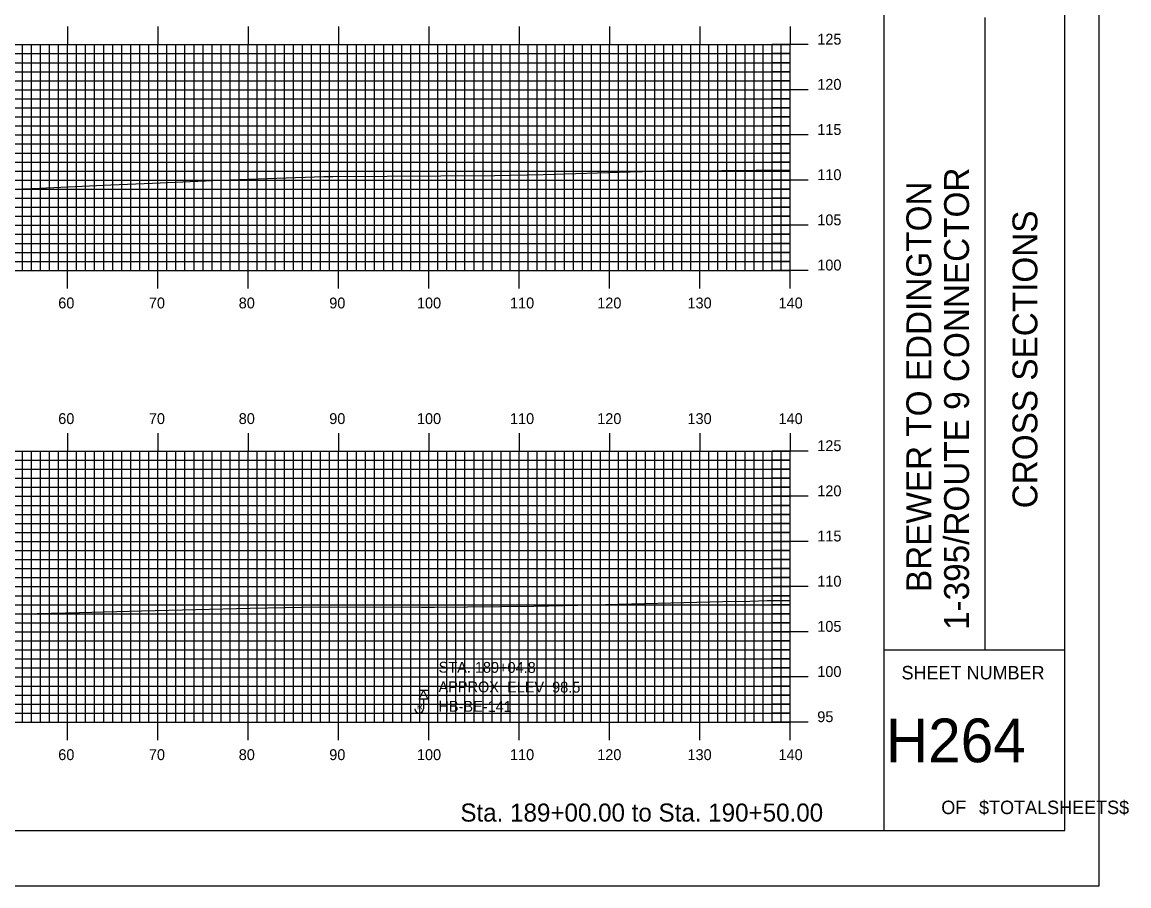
# Model space of a CAD drawing. Extents: x 1788156 to 1788500, y 442591 to 442811.
# Drawn here: x 1788377.1 to 1788499.6, y 442590.5 to 442686.2 of the extents above; entities that cross this region are included whole.
import ezdxf

# ---------------------------------------------------------------- set-up
doc = ezdxf.new("R2010")
doc.units = 0
for name, color, linetype in [('BORDER', 7, 'Continuous'), ('BORING - NO REFUSAL', 7, 'Continuous'), ('BORING - REFUSAL', 7, 'Continuous'), ('H_V ANNOTATION', 7, 'Continuous'), ('MAJOR', 7, 'Continuous'), ('MINOR', 7, 'Continuous'), ('PLOT BOUNDARY', 7, 'Continuous'), ('S_Roadway_Centerline', 7, 'Continuous')]:
    doc.layers.add(name, color=color, linetype=linetype)

msp = doc.modelspace()

# ---------------------------------------------------------------- linework, layer by layer
at = {"layer": 'BORDER'}
for p, q in [((1788472.53, 442596.67), (1788472.53, 442806.67)), ((1788483.71, 442616.67), (1788483.71, 442686.67)), ((1788472.53, 442616.67), (1788492.53, 442616.67))]:
    msp.add_line(p, q, dxfattribs=at)
msp.add_lwpolyline([(1788172.53, 442596.67), (1788492.53, 442596.67), (1788492.53, 442806.67), (1788172.53, 442806.67)], close=True, dxfattribs=at)
at = {"layer": 'BORING - NO REFUSAL'}
for p, q in [((1788422.01, 442612.17), (1788421.05, 442612.17)), ((1788421.53, 442611.21), (1788421.53, 442610.15))]:
    msp.add_line(p, q, dxfattribs=at)
msp.add_lwpolyline([(1788421.53, 442612.17), (1788422.01, 442611.21), (1788421.05, 442611.21)], close=True, dxfattribs=at)
msp.add_arc((1788421.05, 442610.15), 0.485, 180, 0, dxfattribs=at)
at = {"layer": 'MAJOR'}
for p, q in [((1788382.13, 442685.67), (1788382.13, 442683.67)), ((1788392.13, 442685.67), (1788392.13, 442683.67)), ((1788402.13, 442685.67), (1788402.13, 442683.67)), ((1788412.13, 442685.67), (1788412.13, 442683.67)), ((1788422.13, 442685.67), (1788422.13, 442683.67)), ((1788432.13, 442685.67), (1788432.13, 442683.67)), ((1788442.13, 442685.67), (1788442.13, 442683.67)), ((1788452.13, 442685.67), (1788452.13, 442683.67)), ((1788462.13, 442685.67), (1788462.13, 442683.67)), ((1788182.13, 442683.67), (1788462.13, 442683.67)), ((1788182.13, 442683.67), (1788462.13, 442683.67)), ((1788382.13, 442658.67), (1788382.13, 442683.67)), ((1788392.13, 442658.67), (1788392.13, 442683.67)), ((1788402.13, 442658.67), (1788402.13, 442683.67)), ((1788412.13, 442658.67), (1788412.13, 442683.67)), ((1788422.13, 442658.67), (1788422.13, 442683.67)), ((1788432.13, 442658.67), (1788432.13, 442683.67)), ((1788442.13, 442658.67), (1788442.13, 442683.67)), ((1788452.13, 442658.67), (1788452.13, 442683.67)), ((1788464.13, 442683.67), (1788460.13, 442683.67)), ((1788462.13, 442658.67), (1788462.13, 442683.67)), ((1788462.13, 442658.67), (1788462.13, 442683.67)), ((1788182.13, 442678.67), (1788462.13, 442678.67)), ((1788464.13, 442678.67), (1788460.13, 442678.67)), ((1788182.13, 442673.67), (1788462.13, 442673.67)), ((1788464.13, 442673.67), (1788460.13, 442673.67)), ((1788182.13, 442668.67), (1788462.13, 442668.67)), ((1788464.13, 442668.67), (1788460.13, 442668.67)), ((1788182.13, 442663.67), (1788462.13, 442663.67)), ((1788464.13, 442663.67), (1788460.13, 442663.67)), ((1788182.13, 442658.67), (1788462.13, 442658.67)), ((1788182.13, 442658.67), (1788462.13, 442658.67)), ((1788382.13, 442656.66), (1788382.13, 442658.67)), ((1788392.13, 442656.66), (1788392.13, 442658.67)), ((1788402.13, 442656.66), (1788402.13, 442658.67)), ((1788412.13, 442656.66), (1788412.13, 442658.67)), ((1788422.13, 442656.66), (1788422.13, 442658.67)), ((1788432.13, 442656.66), (1788432.13, 442658.67)), ((1788442.13, 442656.66), (1788442.13, 442658.67)), ((1788452.13, 442656.66), (1788452.13, 442658.67)), ((1788464.13, 442658.67), (1788460.13, 442658.67)), ((1788462.13, 442656.66), (1788462.13, 442658.67)), ((1788382.13, 442640.67), (1788382.13, 442638.67)), ((1788392.13, 442640.67), (1788392.13, 442638.67)), ((1788402.13, 442640.67), (1788402.13, 442638.67)), ((1788412.13, 442640.67), (1788412.13, 442638.67)), ((1788422.13, 442640.67), (1788422.13, 442638.67)), ((1788432.13, 442640.67), (1788432.13, 442638.67)), ((1788442.13, 442640.67), (1788442.13, 442638.67)), ((1788452.13, 442640.67), (1788452.13, 442638.67)), ((1788462.13, 442640.67), (1788462.13, 442638.67)), ((1788182.13, 442638.67), (1788462.13, 442638.67)), ((1788182.13, 442638.67), (1788462.13, 442638.67)), ((1788382.13, 442608.67), (1788382.13, 442638.67)), ((1788392.13, 442608.67), (1788392.13, 442638.67)), ((1788402.13, 442608.67), (1788402.13, 442638.67)), ((1788412.13, 442608.67), (1788412.13, 442638.67)), ((1788422.13, 442608.67), (1788422.13, 442638.67)), ((1788432.13, 442608.67), (1788432.13, 442638.67)), ((1788442.13, 442608.67), (1788442.13, 442638.67)), ((1788452.13, 442608.67), (1788452.13, 442638.67)), ((1788464.13, 442638.67), (1788460.13, 442638.67)), ((1788462.13, 442608.67), (1788462.13, 442638.67)), ((1788462.13, 442608.67), (1788462.13, 442638.67)), ((1788182.13, 442633.67), (1788462.13, 442633.67)), ((1788464.13, 442633.67), (1788460.13, 442633.67)), ((1788182.13, 442628.67), (1788462.13, 442628.67)), ((1788464.13, 442628.67), (1788460.13, 442628.67)), ((1788182.13, 442623.67), (1788462.13, 442623.67)), ((1788464.13, 442623.67), (1788460.13, 442623.67)), ((1788182.13, 442618.67), (1788462.13, 442618.67)), ((1788464.13, 442618.67), (1788460.13, 442618.67)), ((1788182.13, 442613.67), (1788462.13, 442613.67)), ((1788464.13, 442613.67), (1788460.13, 442613.67)), ((1788182.13, 442608.67), (1788462.13, 442608.67)), ((1788182.13, 442608.67), (1788462.13, 442608.67)), ((1788382.13, 442606.66), (1788382.13, 442608.67)), ((1788392.13, 442606.66), (1788392.13, 442608.67)), ((1788402.13, 442606.66), (1788402.13, 442608.67)), ((1788412.13, 442606.66), (1788412.13, 442608.67)), ((1788422.13, 442606.66), (1788422.13, 442608.67)), ((1788432.13, 442606.66), (1788432.13, 442608.67)), ((1788442.13, 442606.66), (1788442.13, 442608.67)), ((1788452.13, 442606.66), (1788452.13, 442608.67)), ((1788464.13, 442608.67), (1788460.13, 442608.67)), ((1788462.13, 442606.66), (1788462.13, 442608.67))]:
    msp.add_line(p, q, dxfattribs=at)
at = {"layer": 'MINOR'}
for p, q in [((1788377.13, 442658.67), (1788377.13, 442683.67)), ((1788378.13, 442658.67), (1788378.13, 442683.67)), ((1788379.13, 442658.67), (1788379.13, 442683.67)), ((1788380.13, 442658.67), (1788380.13, 442683.67)), ((1788381.13, 442658.67), (1788381.13, 442683.67)), ((1788383.13, 442658.67), (1788383.13, 442683.67)), ((1788384.13, 442658.67), (1788384.13, 442683.67)), ((1788385.13, 442658.67), (1788385.13, 442683.67)), ((1788386.13, 442658.67), (1788386.13, 442683.67)), ((1788387.13, 442658.67), (1788387.13, 442683.67)), ((1788388.13, 442658.67), (1788388.13, 442683.67)), ((1788389.13, 442658.67), (1788389.13, 442683.67)), ((1788390.13, 442658.67), (1788390.13, 442683.67)), ((1788391.13, 442658.67), (1788391.13, 442683.67)), ((1788393.13, 442658.67), (1788393.13, 442683.67)), ((1788394.13, 442658.67), (1788394.13, 442683.67)), ((1788395.13, 442658.67), (1788395.13, 442683.67)), ((1788396.13, 442658.67), (1788396.13, 442683.67)), ((1788397.13, 442658.67), (1788397.13, 442683.67)), ((1788398.13, 442658.67), (1788398.13, 442683.67)), ((1788399.13, 442658.67), (1788399.13, 442683.67)), ((1788400.13, 442658.67), (1788400.13, 442683.67)), ((1788401.13, 442658.67), (1788401.13, 442683.67)), ((1788403.13, 442658.67), (1788403.13, 442683.67)), ((1788404.13, 442658.67), (1788404.13, 442683.67)), ((1788405.13, 442658.67), (1788405.13, 442683.67)), ((1788406.13, 442658.67), (1788406.13, 442683.67)), ((1788407.13, 442658.67), (1788407.13, 442683.67)), ((1788408.13, 442658.67), (1788408.13, 442683.67)), ((1788409.13, 442658.67), (1788409.13, 442683.67)), ((1788410.13, 442658.67), (1788410.13, 442683.67)), ((1788411.13, 442658.67), (1788411.13, 442683.67)), ((1788413.13, 442658.67), (1788413.13, 442683.67)), ((1788414.13, 442658.67), (1788414.13, 442683.67)), ((1788415.13, 442658.67), (1788415.13, 442683.67)), ((1788416.13, 442658.67), (1788416.13, 442683.67)), ((1788417.13, 442658.67), (1788417.13, 442683.67)), ((1788418.13, 442658.67), (1788418.13, 442683.67)), ((1788419.13, 442658.67), (1788419.13, 442683.67)), ((1788420.13, 442658.67), (1788420.13, 442683.67)), ((1788421.13, 442658.67), (1788421.13, 442683.67)), ((1788423.13, 442658.67), (1788423.13, 442683.67)), ((1788424.13, 442658.67), (1788424.13, 442683.67)), ((1788425.13, 442658.67), (1788425.13, 442683.67)), ((1788426.13, 442658.67), (1788426.13, 442683.67)), ((1788427.13, 442658.67), (1788427.13, 442683.67)), ((1788428.13, 442658.67), (1788428.13, 442683.67)), ((1788429.13, 442658.67), (1788429.13, 442683.67)), ((1788430.13, 442658.67), (1788430.13, 442683.67)), ((1788431.13, 442658.67), (1788431.13, 442683.67)), ((1788433.13, 442658.67), (1788433.13, 442683.67)), ((1788434.13, 442658.67), (1788434.13, 442683.67)), ((1788435.13, 442658.67), (1788435.13, 442683.67)), ((1788436.13, 442658.67), (1788436.13, 442683.67)), ((1788437.13, 442658.67), (1788437.13, 442683.67)), ((1788438.13, 442658.67), (1788438.13, 442683.67)), ((1788439.13, 442658.67), (1788439.13, 442683.67)), ((1788440.13, 442658.67), (1788440.13, 442683.67)), ((1788441.13, 442658.67), (1788441.13, 442683.67)), ((1788443.13, 442658.67), (1788443.13, 442683.67)), ((1788444.13, 442658.67), (1788444.13, 442683.67)), ((1788445.13, 442658.67), (1788445.13, 442683.67)), ((1788446.13, 442658.67), (1788446.13, 442683.67)), ((1788447.13, 442658.67), (1788447.13, 442683.67)), ((1788448.13, 442658.67), (1788448.13, 442683.67)), ((1788449.13, 442658.67), (1788449.13, 442683.67)), ((1788450.13, 442658.67), (1788450.13, 442683.67)), ((1788451.13, 442658.67), (1788451.13, 442683.67)), ((1788453.13, 442658.67), (1788453.13, 442683.67)), ((1788454.13, 442658.67), (1788454.13, 442683.67)), ((1788455.13, 442658.67), (1788455.13, 442683.67)), ((1788456.13, 442658.67), (1788456.13, 442683.67)), ((1788457.13, 442658.67), (1788457.13, 442683.67)), ((1788458.13, 442658.67), (1788458.13, 442683.67)), ((1788459.13, 442658.67), (1788459.13, 442683.67)), ((1788460.13, 442658.67), (1788460.13, 442683.67)), ((1788461.13, 442658.67), (1788461.13, 442683.67)), ((1788182.13, 442682.67), (1788462.13, 442682.67)), ((1788182.13, 442681.67), (1788462.13, 442681.67)), ((1788462.13, 442682.67), (1788460.13, 442682.67)), ((1788462.13, 442681.67), (1788460.13, 442681.67)), ((1788182.13, 442680.67), (1788462.13, 442680.67)), ((1788462.13, 442680.67), (1788460.13, 442680.67)), ((1788182.13, 442679.67), (1788462.13, 442679.67)), ((1788462.13, 442679.67), (1788460.13, 442679.67)), ((1788182.13, 442677.67), (1788462.13, 442677.67)), ((1788462.13, 442677.67), (1788460.13, 442677.67)), ((1788182.13, 442676.67), (1788462.13, 442676.67)), ((1788182.13, 442675.67), (1788462.13, 442675.67)), ((1788462.13, 442676.67), (1788460.13, 442676.67)), ((1788462.13, 442675.67), (1788460.13, 442675.67)), ((1788182.13, 442674.67), (1788462.13, 442674.67)), ((1788462.13, 442674.67), (1788460.13, 442674.67)), ((1788182.13, 442672.67), (1788462.13, 442672.67)), ((1788462.13, 442672.67), (1788460.13, 442672.67)), ((1788182.13, 442671.67), (1788462.13, 442671.67)), ((1788182.13, 442670.67), (1788462.13, 442670.67)), ((1788462.13, 442671.67), (1788460.13, 442671.67)), ((1788462.13, 442670.67), (1788460.13, 442670.67)), ((1788182.13, 442669.67), (1788462.13, 442669.67)), ((1788462.13, 442669.67), (1788460.13, 442669.67)), ((1788182.13, 442667.67), (1788462.13, 442667.67)), ((1788462.13, 442667.67), (1788460.13, 442667.67)), ((1788182.13, 442666.67), (1788462.13, 442666.67)), ((1788462.13, 442666.67), (1788460.13, 442666.67)), ((1788182.13, 442665.67), (1788462.13, 442665.67)), ((1788182.13, 442664.67), (1788462.13, 442664.67)), ((1788462.13, 442665.67), (1788460.13, 442665.67)), ((1788462.13, 442664.67), (1788460.13, 442664.67)), ((1788182.13, 442662.67), (1788462.13, 442662.67)), ((1788462.13, 442662.67), (1788460.13, 442662.67)), ((1788182.13, 442661.67), (1788462.13, 442661.67)), ((1788462.13, 442661.67), (1788460.13, 442661.67)), ((1788182.13, 442660.67), (1788462.13, 442660.67)), ((1788182.13, 442659.67), (1788462.13, 442659.67)), ((1788462.13, 442660.67), (1788460.13, 442660.67)), ((1788462.13, 442659.67), (1788460.13, 442659.67)), ((1788182.13, 442637.67), (1788462.13, 442637.67)), ((1788377.13, 442608.67), (1788377.13, 442638.67)), ((1788378.13, 442608.67), (1788378.13, 442638.67)), ((1788379.13, 442608.67), (1788379.13, 442638.67)), ((1788380.13, 442608.67), (1788380.13, 442638.67)), ((1788381.13, 442608.67), (1788381.13, 442638.67)), ((1788383.13, 442608.67), (1788383.13, 442638.67)), ((1788384.13, 442608.67), (1788384.13, 442638.67)), ((1788385.13, 442608.67), (1788385.13, 442638.67)), ((1788386.13, 442608.67), (1788386.13, 442638.67)), ((1788387.13, 442608.67), (1788387.13, 442638.67)), ((1788388.13, 442608.67), (1788388.13, 442638.67)), ((1788389.13, 442608.67), (1788389.13, 442638.67)), ((1788390.13, 442608.67), (1788390.13, 442638.67)), ((1788391.13, 442608.67), (1788391.13, 442638.67)), ((1788393.13, 442608.67), (1788393.13, 442638.67)), ((1788394.13, 442608.67), (1788394.13, 442638.67)), ((1788395.13, 442608.67), (1788395.13, 442638.67)), ((1788396.13, 442608.67), (1788396.13, 442638.67)), ((1788397.13, 442608.67), (1788397.13, 442638.67)), ((1788398.13, 442608.67), (1788398.13, 442638.67)), ((1788399.13, 442608.67), (1788399.13, 442638.67)), ((1788400.13, 442608.67), (1788400.13, 442638.67)), ((1788401.13, 442608.67), (1788401.13, 442638.67)), ((1788403.13, 442608.67), (1788403.13, 442638.67)), ((1788404.13, 442608.67), (1788404.13, 442638.67)), ((1788405.13, 442608.67), (1788405.13, 442638.67)), ((1788406.13, 442608.67), (1788406.13, 442638.67)), ((1788407.13, 442608.67), (1788407.13, 442638.67)), ((1788408.13, 442608.67), (1788408.13, 442638.67)), ((1788409.13, 442608.67), (1788409.13, 442638.67)), ((1788410.13, 442608.67), (1788410.13, 442638.67)), ((1788411.13, 442608.67), (1788411.13, 442638.67)), ((1788413.13, 442608.67), (1788413.13, 442638.67)), ((1788414.13, 442608.67), (1788414.13, 442638.67)), ((1788415.13, 442608.67), (1788415.13, 442638.67)), ((1788416.13, 442608.67), (1788416.13, 442638.67)), ((1788417.13, 442608.67), (1788417.13, 442638.67)), ((1788418.13, 442608.67), (1788418.13, 442638.67)), ((1788419.13, 442608.67), (1788419.13, 442638.67)), ((1788420.13, 442608.67), (1788420.13, 442638.67)), ((1788421.13, 442608.67), (1788421.13, 442638.67)), ((1788423.13, 442608.67), (1788423.13, 442638.67)), ((1788424.13, 442608.67), (1788424.13, 442638.67)), ((1788425.13, 442608.67), (1788425.13, 442638.67)), ((1788426.13, 442608.67), (1788426.13, 442638.67)), ((1788427.13, 442608.67), (1788427.13, 442638.67)), ((1788428.13, 442608.67), (1788428.13, 442638.67)), ((1788429.13, 442608.67), (1788429.13, 442638.67)), ((1788430.13, 442608.67), (1788430.13, 442638.67)), ((1788431.13, 442608.67), (1788431.13, 442638.67)), ((1788433.13, 442608.67), (1788433.13, 442638.67)), ((1788434.13, 442608.67), (1788434.13, 442638.67)), ((1788435.13, 442608.67), (1788435.13, 442638.67)), ((1788436.13, 442608.67), (1788436.13, 442638.67)), ((1788437.13, 442608.67), (1788437.13, 442638.67)), ((1788438.13, 442608.67), (1788438.13, 442638.67)), ((1788439.13, 442608.67), (1788439.13, 442638.67)), ((1788440.13, 442608.67), (1788440.13, 442638.67)), ((1788441.13, 442608.67), (1788441.13, 442638.67)), ((1788443.13, 442608.67), (1788443.13, 442638.67)), ((1788444.13, 442608.67), (1788444.13, 442638.67)), ((1788445.13, 442608.67), (1788445.13, 442638.67)), ((1788446.13, 442608.67), (1788446.13, 442638.67)), ((1788447.13, 442608.67), (1788447.13, 442638.67)), ((1788448.13, 442608.67), (1788448.13, 442638.67)), ((1788449.13, 442608.67), (1788449.13, 442638.67)), ((1788450.13, 442608.67), (1788450.13, 442638.67)), ((1788451.13, 442608.67), (1788451.13, 442638.67)), ((1788453.13, 442608.67), (1788453.13, 442638.67)), ((1788454.13, 442608.67), (1788454.13, 442638.67)), ((1788455.13, 442608.67), (1788455.13, 442638.67)), ((1788456.13, 442608.67), (1788456.13, 442638.67)), ((1788457.13, 442608.67), (1788457.13, 442638.67)), ((1788458.13, 442608.67), (1788458.13, 442638.67)), ((1788459.13, 442608.67), (1788459.13, 442638.67)), ((1788460.13, 442608.67), (1788460.13, 442638.67)), ((1788462.13, 442637.67), (1788460.13, 442637.67)), ((1788461.13, 442608.67), (1788461.13, 442638.67)), ((1788182.13, 442636.67), (1788462.13, 442636.67)), ((1788462.13, 442636.67), (1788460.13, 442636.67)), ((1788182.13, 442635.67), (1788462.13, 442635.67)), ((1788462.13, 442635.67), (1788460.13, 442635.67)), ((1788182.13, 442634.67), (1788462.13, 442634.67)), ((1788462.13, 442634.67), (1788460.13, 442634.67)), ((1788182.13, 442632.67), (1788462.13, 442632.67)), ((1788462.13, 442632.67), (1788460.13, 442632.67)), ((1788182.13, 442631.67), (1788462.13, 442631.67)), ((1788462.13, 442631.67), (1788460.13, 442631.67)), ((1788182.13, 442630.67), (1788462.13, 442630.67)), ((1788462.13, 442630.67), (1788460.13, 442630.67)), ((1788182.13, 442629.67), (1788462.13, 442629.67)), ((1788462.13, 442629.67), (1788460.13, 442629.67)), ((1788182.13, 442627.67), (1788462.13, 442627.67)), ((1788182.13, 442626.67), (1788462.13, 442626.67)), ((1788462.13, 442627.67), (1788460.13, 442627.67)), ((1788462.13, 442626.67), (1788460.13, 442626.67)), ((1788182.13, 442625.67), (1788462.13, 442625.67)), ((1788462.13, 442625.67), (1788460.13, 442625.67)), ((1788182.13, 442624.67), (1788462.13, 442624.67)), ((1788462.13, 442624.67), (1788460.13, 442624.67)), ((1788182.13, 442622.67), (1788462.13, 442622.67)), ((1788182.13, 442621.67), (1788462.13, 442621.67)), ((1788462.13, 442622.67), (1788460.13, 442622.67)), ((1788462.13, 442621.67), (1788460.13, 442621.67)), ((1788182.13, 442620.67), (1788462.13, 442620.67)), ((1788462.13, 442620.67), (1788460.13, 442620.67)), ((1788182.13, 442619.67), (1788462.13, 442619.67)), ((1788462.13, 442619.67), (1788460.13, 442619.67)), ((1788182.13, 442617.67), (1788462.13, 442617.67)), ((1788462.13, 442617.67), (1788460.13, 442617.67)), ((1788182.13, 442616.67), (1788462.13, 442616.67)), ((1788182.13, 442615.67), (1788462.13, 442615.67)), ((1788462.13, 442616.67), (1788460.13, 442616.67)), ((1788462.13, 442615.67), (1788460.13, 442615.67)), ((1788182.13, 442614.67), (1788462.13, 442614.67)), ((1788462.13, 442614.67), (1788460.13, 442614.67)), ((1788182.13, 442612.67), (1788462.13, 442612.67)), ((1788462.13, 442612.67), (1788460.13, 442612.67)), ((1788182.13, 442611.67), (1788462.13, 442611.67)), ((1788182.13, 442610.67), (1788462.13, 442610.67)), ((1788462.13, 442611.67), (1788460.13, 442611.67)), ((1788462.13, 442610.67), (1788460.13, 442610.67)), ((1788182.13, 442609.67), (1788462.13, 442609.67)), ((1788462.13, 442609.67), (1788460.13, 442609.67))]:
    msp.add_line(p, q, dxfattribs=at)
at = {"layer": 'PLOT BOUNDARY'}
msp.add_lwpolyline([(1788156.34, 442590.55), (1788496.34, 442590.55), (1788496.34, 442810.55), (1788156.34, 442810.55)], close=True, dxfattribs=at)
at = {"layer": 'S_Roadway_Centerline'}
for points in [[(1788372.66, 442667.51), (1788379.02, 442667.79), (1788386.91, 442668.15), (1788391.54, 442668.33), (1788399.08, 442668.65), (1788410.52, 442669.07), (1788410.91, 442669.08), (1788411.54, 442669.08), (1788429.45, 442669.17), (1788434.79, 442669.28), (1788444.43, 442669.58), (1788448.49, 442669.69), (1788454.55, 442669.73), (1788462.13, 442669.81)], [(1788373.99, 442620.57), (1788383.47, 442620.81), (1788390.33, 442620.98), (1788402.36, 442621.27), (1788410.11, 442621.45), (1788421.3, 442621.39), (1788422.76, 442621.4), (1788433.74, 442621.49), (1788440.25, 442621.65), (1788454.66, 442622.02), (1788457.68, 442622.08), (1788459.58, 442622.12), (1788462.13, 442622.12)]]:
    msp.add_lwpolyline(points, dxfattribs=at)

# ---------------------------------------------------------------- texts
at = {"layer": 'BORDER'}
for s, p in [('1-395/ROUTE 9 CONNECTOR', (1788481.93, 442618.87)), ('BREWER TO EDDINGTON', (1788477.75, 442623.07)), ('CROSS SECTIONS', (1788489.5, 442632.34))]:
    msp.add_text(s, height=2.7557, rotation=90, dxfattribs=at).set_placement(p)
for s, height, p in [('SHEET NUMBER', 1.4905, (1788474.46, 442613.4)), ('H264', 4.839, (1788472.74, 442604.23)), ('OF', 1.491, (1788478.86, 442598.49)), ('$TOTALSHEETS$', 1.4905, (1788483.04, 442598.49))]:
    msp.add_text(s, height=height, dxfattribs=at).set_placement(p)
at = {"layer": 'BORING - NO REFUSAL'}
msp.add_text('R', height=0.64, dxfattribs=at).set_placement((1788420.82, 442610.09))
at = {"layer": 'BORING - REFUSAL'}
for s, p in [('STA. 189+04.8', (1788423.21, 442614.15)), ('APPROX. ELEV. 98.5', (1788423.2, 442611.99)), ('HB-BE-141', (1788423.19, 442609.83))]:
    msp.add_text(s, height=1.2, rotation=359.8142, dxfattribs=at).set_placement(p)
at = {"layer": 'H_V ANNOTATION'}
for s, height, p in [('125', 1.2, (1788465.13, 442683.67)), ('120', 1.2, (1788465.13, 442678.67)), ('115', 1.2, (1788465.13, 442673.67)), ('110', 1.2, (1788465.13, 442668.67)), ('105', 1.2, (1788465.13, 442663.67)), ('100', 1.2, (1788465.13, 442658.67)), ('60', 1.2, (1788381.1, 442654.47)), ('70', 1.2, (1788391.13, 442654.47)), ('80', 1.2, (1788401.08, 442654.47)), ('90', 1.2, (1788411.1, 442654.47)), ('100', 1.2, (1788420.81, 442654.47)), ('110', 1.2, (1788431.11, 442654.47)), ('120', 1.2, (1788440.77, 442654.47)), ('130', 1.2, (1788450.76, 442654.47)), ('140', 1.2, (1788460.84, 442654.47)), ('60', 1.2, (1788381.1, 442641.67)), ('70', 1.2, (1788391.13, 442641.67)), ('80', 1.2, (1788401.08, 442641.67)), ('90', 1.2, (1788411.1, 442641.67)), ('100', 1.2, (1788420.81, 442641.67)), ('110', 1.2, (1788431.11, 442641.67)), ('120', 1.2, (1788440.77, 442641.67)), ('130', 1.2, (1788450.76, 442641.67)), ('140', 1.2, (1788460.84, 442641.67)), ('125', 1.2, (1788465.13, 442638.67)), ('120', 1.2, (1788465.13, 442633.67)), ('115', 1.2, (1788465.13, 442628.67)), ('110', 1.2, (1788465.13, 442623.67)), ('105', 1.2, (1788465.13, 442618.67)), ('100', 1.2, (1788465.13, 442613.67)), ('95', 1.2, (1788465.13, 442608.67)), ('60', 1.2, (1788381.1, 442604.47)), ('70', 1.2, (1788391.13, 442604.47)), ('80', 1.2, (1788401.08, 442604.47)), ('90', 1.2, (1788411.1, 442604.47)), ('100', 1.2, (1788420.81, 442604.47)), ('110', 1.2, (1788431.11, 442604.47)), ('120', 1.2, (1788440.77, 442604.47)), ('130', 1.2, (1788450.76, 442604.47)), ('140', 1.2, (1788460.84, 442604.47)), ('Sta. 189+00.00 to Sta. 190+50.00', 2.0004, (1788425.62, 442597.66))]:
    msp.add_text(s, height=height, dxfattribs=at).set_placement(p)

doc.saveas('drawing.dxf')
